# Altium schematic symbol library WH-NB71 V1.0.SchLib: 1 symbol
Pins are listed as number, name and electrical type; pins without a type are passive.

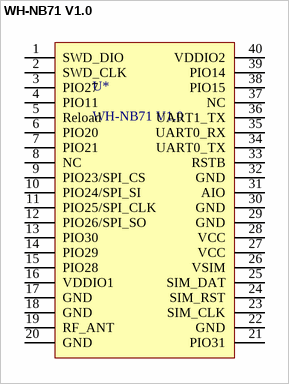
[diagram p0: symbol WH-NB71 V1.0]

## WH-NB71 V1.0
designator U*
footprint WH-NB71 V1.0
pins: 1 SWD_DIO, 2 SWD_CLK, 3 PIO27, 4 PIO11, 5 Reload, 6 PIO20, 7 PIO21, 8 NC, 9 PIO23/SPI_CS, 10 PIO24/SPI_SI, 11 PIO25/SPI_CLK, 12 PIO26/SPI_SO, 13 PIO30, 14 PIO29, 15 PIO28, 16 VDDIO1, 17 GND, 18 GND, 19 RF_ANT, 20 GND, 21 PIO31, 22 GND, 23 SIM_CLK, 24 SIM_RST, 25 SIM_DAT, 26 VSIM, 27 VCC, 28 VCC, 29 GND, 30 GND, 31 AIO, 32 GND, 33 RSTB, 34 UART0_TX, 35 UART0_RX, 36 UART1_TX, 37 NC, 38 PIO15, 39 PIO14, 40 VDDIO2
